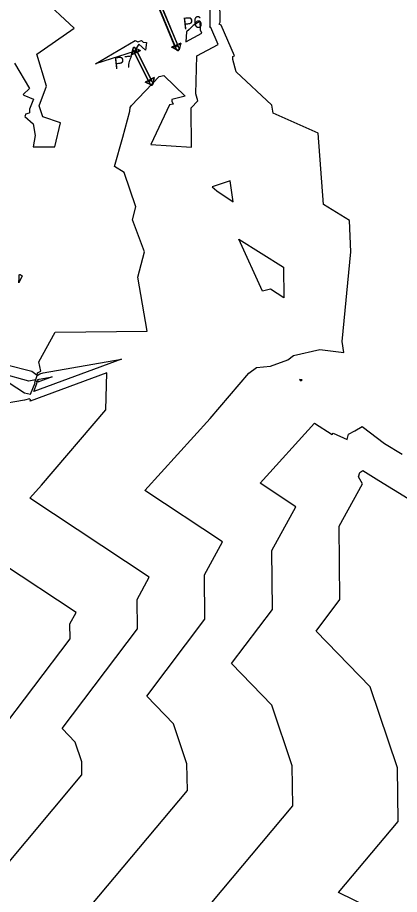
# Model space of a CAD drawing. Extents: x -549394 to -546608, y -1037055 to -1033629.
# Drawn here: x -547438 to -547324.6, y -1035525.4 to -1035265.1 of the extents above; entities that cross this region are included whole.
import ezdxf

# ---------------------------------------------------------------- set-up
doc = ezdxf.new("R2010")
doc.units = 0
for name, color, linetype in [('hlavni_vrst', 7, 'Continuous'), ('norm_vrst', 7, 'Continuous'), ('x_popis_C14', 7, 'Continuous'), ('x_propustek', 7, 'Continuous')]:
    doc.layers.add(name, color=color, linetype=linetype)

msp = doc.modelspace()

# ---------------------------------------------------------------- linework, layer by layer
at = {"layer": 'hlavni_vrst'}
for p, q in [((-547427.7, -1035371.77), (-547432.03, -1035373.37)), ((-547432.03, -1035373.37), (-547431.85, -1035372.89)), ((-547431.97, -1035372.6), (-547431.9, -1035372.55)), ((-547431.97, -1035372.82), (-547431.97, -1035372.6)), ((-547431.85, -1035372.89), (-547431.97, -1035372.82)), ((-547431.9, -1035372.55), (-547431.57, -1035372.45)), ((-547431.57, -1035372.45), (-547427.7, -1035371.77)), ((-547365.95, -1035403.31), (-547349.87, -1035385.5)), ((-547349.87, -1035385.5), (-547344.57, -1035388.84)), ((-547337.93, -1035387.82), (-547335.7, -1035386.54)), ((-547335.7, -1035386.54), (-547329.05, -1035391.52)), ((-547344.57, -1035388.84), (-547344.36, -1035388.52)), ((-547344.36, -1035388.52), (-547340.2, -1035390.38)), ((-547340.2, -1035390.38), (-547339.78, -1035388.83)), ((-547339.78, -1035388.83), (-547337.93, -1035387.82)), ((-547329.05, -1035391.52), (-547323.87, -1035394.76)), ((-547355.36, -1035410.32), (-547365.95, -1035403.31)), ((-547362.55, -1035423.36), (-547355.36, -1035410.32)), ((-547362.34, -1035440.8), (-547362.55, -1035423.36)), ((-547374.53, -1035456.91), (-547362.34, -1035440.8)), ((-547362.54, -1035469.25), (-547374.53, -1035456.91)), ((-547356.48, -1035487.24), (-547362.54, -1035469.25)), ((-547356.3, -1035499.12), (-547356.48, -1035487.24)), ((-547383.4, -1035531.44), (-547356.3, -1035499.12))]:
    msp.add_line(p, q, dxfattribs=at)
at = {"layer": 'norm_vrst'}
for p, q in [((-547380.81, -1035267.64), (-547380.88, -1035253.24)), ((-547421.19, -1035268.25), (-547432.95, -1035257.28)), ((-547377.89, -1035266.54), (-547377.92, -1035259.76)), ((-547383.75, -1035266.15), (-547385.92, -1035267.52)), ((-547383.74, -1035268.75), (-547383.75, -1035266.15)), ((-547378.18, -1035267.11), (-547377.89, -1035266.54)), ((-547432.32, -1035276.03), (-547421.19, -1035268.25)), ((-547387.88, -1035269.32), (-547388.08, -1035272.29)), ((-547387.06, -1035268.71), (-547387.88, -1035269.32)), ((-547385.92, -1035267.52), (-547387.06, -1035268.71)), ((-547383.77, -1035268.8), (-547383.74, -1035268.75)), ((-547383.71, -1035268.83), (-547383.77, -1035268.8)), ((-547383.31, -1035269.73), (-547383.71, -1035268.83)), ((-547380.97, -1035267.96), (-547380.81, -1035267.64)), ((-547380.66, -1035268.12), (-547380.97, -1035267.96)), ((-547378.46, -1035273.09), (-547380.66, -1035268.12)), ((-547377.61, -1035267.4), (-547378.18, -1035267.11)), ((-547373.61, -1035276.45), (-547377.61, -1035267.4)), ((-547414.86, -1035278.87), (-547403.07, -1035271.98)), ((-547403.07, -1035271.98), (-547402.33, -1035272.33)), ((-547402.33, -1035272.33), (-547401.26, -1035271.97)), ((-547401.26, -1035271.97), (-547400.7, -1035272.4)), ((-547388.08, -1035272.29), (-547383.31, -1035269.73)), ((-547402.04, -1035273.04), (-547403.41, -1035275.22)), ((-547400.06, -1035274.8), (-547402.04, -1035273.04)), ((-547400.7, -1035272.4), (-547399.73, -1035272.53)), ((-547399.73, -1035272.53), (-547400.06, -1035274.8)), ((-547384.79, -1035276.49), (-547378.46, -1035273.09)), ((-547429.44, -1035285.46), (-547432.32, -1035276.03)), ((-547403.41, -1035275.22), (-547414.86, -1035278.87)), ((-547385.1, -1035287.74), (-547384.79, -1035276.49)), ((-547374.1, -1035277.54), (-547374.08, -1035276.7)), ((-547374.08, -1035276.7), (-547373.61, -1035276.45)), ((-547438.93, -1035278.69), (-547434.43, -1035286.23)), ((-547373.07, -1035281.22), (-547374.1, -1035277.54)), ((-547404.2, -1035291.19), (-547395.97, -1035282.66)), ((-547395.97, -1035282.66), (-547394.56, -1035282.33)), ((-547394.56, -1035282.33), (-547388.3, -1035288.42)), ((-547362.51, -1035291.15), (-547373.07, -1035281.22)), ((-547434.43, -1035286.23), (-547436.33, -1035288)), ((-547431.59, -1035291.29), (-547429.44, -1035285.46)), ((-547384.51, -1035289.83), (-547385.1, -1035287.74)), ((-547436.33, -1035288), (-547436.27, -1035288.03)), ((-547436.27, -1035288.03), (-547436.19, -1035288.2)), ((-547436.19, -1035288.2), (-547433.28, -1035289.38)), ((-547433.28, -1035289.38), (-547434.45, -1035292.28)), ((-547388.3, -1035288.42), (-547392.24, -1035289.43)), ((-547392.24, -1035289.43), (-547392.22, -1035289.95)), ((-547392.22, -1035289.95), (-547391.81, -1035290.88)), ((-547386.51, -1035291.88), (-547384.51, -1035289.83)), ((-547434.45, -1035292.28), (-547434.5, -1035293.43)), ((-547430.55, -1035294.64), (-547431.59, -1035291.29)), ((-547406.73, -1035300.62), (-547404.64, -1035292.94)), ((-547404.64, -1035292.94), (-547404.6, -1035291.85)), ((-547404.6, -1035291.85), (-547404.2, -1035291.19)), ((-547392.94, -1035290.99), (-547398.47, -1035302.8)), ((-547391.81, -1035290.88), (-547392.94, -1035290.99)), ((-547386.34, -1035303.6), (-547386.51, -1035291.88)), ((-547362.1, -1035293.55), (-547362.51, -1035291.15)), ((-547435.54, -1035293.74), (-547435.86, -1035294.48)), ((-547435.86, -1035294.48), (-547433.33, -1035296.72)), ((-547435.54, -1035293.74), (-547434.5, -1035293.43)), ((-547425.27, -1035296.42), (-547430.55, -1035294.64)), ((-547348.8, -1035299.47), (-547362.1, -1035293.55)), ((-547433.33, -1035296.72), (-547432.75, -1035300.09)), ((-547426.92, -1035303.53), (-547425.27, -1035296.42)), ((-547432.75, -1035300.09), (-547433.38, -1035303.53)), ((-547409.24, -1035309.35), (-547406.73, -1035300.62)), ((-547347.19, -1035320.57), (-547348.8, -1035299.47)), ((-547433.38, -1035303.53), (-547426.92, -1035303.53)), ((-547398.47, -1035302.8), (-547386.34, -1035303.6)), ((-547406.39, -1035311.07), (-547409.24, -1035309.35)), ((-547402.86, -1035321.34), (-547406.39, -1035311.07)), ((-547374.89, -1035313.57), (-547380.23, -1035315.38)), ((-547374.05, -1035319.8), (-547374.89, -1035313.57)), ((-547380.23, -1035315.38), (-547378.83, -1035316.58)), ((-547378.83, -1035316.58), (-547374.05, -1035319.8)), ((-547403.9, -1035325.15), (-547402.86, -1035321.34)), ((-547339.51, -1035325.35), (-547347.19, -1035320.57)), ((-547400.32, -1035334.67), (-547403.9, -1035325.15)), ((-547339.08, -1035334.62), (-547339.51, -1035325.35)), ((-547372.31, -1035330.92), (-547359.1, -1035339.24)), ((-547365.27, -1035346.33), (-547372.31, -1035330.92)), ((-547402.34, -1035342.16), (-547400.32, -1035334.67)), ((-547341.62, -1035361.33), (-547339.08, -1035334.62)), ((-547359.1, -1035339.24), (-547358.95, -1035348.33)), ((-547436.65, -1035341.77), (-547437.66, -1035343.87)), ((-547437.66, -1035343.87), (-547437.55, -1035342.43)), ((-547437.55, -1035342.43), (-547437.52, -1035341.54)), ((-547437.52, -1035341.54), (-547437.29, -1035341.44)), ((-547437.29, -1035341.44), (-547437.24, -1035341.39)), ((-547437.24, -1035341.39), (-547436.65, -1035341.77)), ((-547399.54, -1035358.21), (-547402.34, -1035342.16)), ((-547362.88, -1035345.77), (-547365.27, -1035346.33)), ((-547365.27, -1035346.33), (-547365.27, -1035346.33)), ((-547358.95, -1035348.33), (-547362.88, -1035345.77)), ((-547362.88, -1035345.77), (-547362.88, -1035345.77)), ((-547431.66, -1035367.28), (-547426.86, -1035358.54)), ((-547426.86, -1035358.54), (-547399.54, -1035358.21)), ((-547341.16, -1035364.59), (-547341.62, -1035361.33)), ((-547357.82, -1035366.7), (-547356.05, -1035365.42)), ((-547356.05, -1035365.42), (-547348.25, -1035363.7)), ((-547348.25, -1035363.7), (-547341.16, -1035364.59)), ((-547441.58, -1035368.06), (-547433.73, -1035370.1)), ((-547407.19, -1035366.57), (-547433.16, -1035376.16)), ((-547431.11, -1035370.06), (-547431.66, -1035367.28)), ((-547430.42, -1035370.63), (-547407.19, -1035366.57)), ((-547362.92, -1035368.63), (-547357.82, -1035366.7)), ((-547434.67, -1035373.03), (-547442.43, -1035370.9)), ((-547411.55, -1035370.55), (-547434.3, -1035378.95)), ((-547433.73, -1035370.1), (-547432.23, -1035371.23)), ((-547432.23, -1035371.23), (-547432.06, -1035370.6)), ((-547432.21, -1035371.4), (-547431.36, -1035370.91)), ((-547432.06, -1035370.6), (-547431.11, -1035370.06)), ((-547431.36, -1035370.91), (-547430.42, -1035370.63)), ((-547411.85, -1035381.59), (-547411.55, -1035370.55)), ((-547380.83, -1035384.1), (-547369.34, -1035370.67)), ((-547369.34, -1035370.67), (-547367.1, -1035369.04)), ((-547367.1, -1035369.04), (-547362.92, -1035368.63)), ((-547443.07, -1035371.84), (-547435.93, -1035376.54)), ((-547432.65, -1035372.63), (-547434.67, -1035373.03)), ((-547434.14, -1035376.92), (-547432.81, -1035373.57)), ((-547433.16, -1035376.16), (-547432.28, -1035373.75)), ((-547432.93, -1035373.5), (-547432.65, -1035372.63)), ((-547432.81, -1035373.57), (-547432.93, -1035373.5)), ((-547432.68, -1035372.99), (-547432.55, -1035372.6)), ((-547432.16, -1035373.3), (-547432.68, -1035372.99)), ((-547432.55, -1035372.6), (-547432.38, -1035372)), ((-547432.38, -1035372), (-547432.3, -1035371.72)), ((-547432.32, -1035373.71), (-547432.16, -1035373.3)), ((-547432.28, -1035373.75), (-547432.32, -1035373.71)), ((-547432.3, -1035371.72), (-547432.21, -1035371.4)), ((-547353.94, -1035372.67), (-547354.27, -1035372.53)), ((-547354.27, -1035372.53), (-547354.13, -1035372.79)), ((-547354.13, -1035372.79), (-547353.82, -1035372.97)), ((-547353.48, -1035372.64), (-547353.94, -1035372.67)), ((-547353.82, -1035372.97), (-547353.48, -1035372.64)), ((-547435.93, -1035378.68), (-547448.48, -1035380.87)), ((-547435.93, -1035376.54), (-547434.14, -1035376.92)), ((-547434.46, -1035378.31), (-547435.93, -1035378.68)), ((-547434.17, -1035378.6), (-547434.46, -1035378.31)), ((-547434.3, -1035378.95), (-547434.17, -1035378.6)), ((-547430.92, -1035403.89), (-547411.85, -1035381.59)), ((-547400.18, -1035405.53), (-547380.83, -1035384.1)), ((-547336.39, -1035400.15), (-547335.52, -1035399.59)), ((-547335.52, -1035399.59), (-547330.74, -1035402.58)), ((-547336.81, -1035401.41), (-547336.39, -1035400.15)), ((-547335.6, -1035403.49), (-547336.81, -1035401.41)), ((-547434.41, -1035407.75), (-547430.92, -1035403.89)), ((-547342.57, -1035416.13), (-547335.6, -1035403.49)), ((-547330.74, -1035402.58), (-547322.05, -1035407.85)), ((-547377.12, -1035420.78), (-547400.18, -1035405.53)), ((-547398.89, -1035431.25), (-547434.41, -1035407.75)), ((-547342.31, -1035437.9), (-547342.57, -1035416.13)), ((-547382.53, -1035430.59), (-547377.12, -1035420.78)), ((-547420.65, -1035441.72), (-547442.43, -1035427.31)), ((-547382.37, -1035443.7), (-547382.53, -1035430.59)), ((-547402.51, -1035437.82), (-547398.89, -1035431.25)), ((-547402.4, -1035446.61), (-547402.51, -1035437.82)), ((-547349.39, -1035447.27), (-547342.31, -1035437.9)), ((-547422.49, -1035445.05), (-547420.65, -1035441.72)), ((-547399.66, -1035466.56), (-547382.37, -1035443.7)), ((-547424.79, -1035476.2), (-547402.4, -1035446.61)), ((-547422.44, -1035449.51), (-547422.49, -1035445.05)), ((-547333.36, -1035463.78), (-547349.39, -1035447.27)), ((-547448.7, -1035484.23), (-547422.44, -1035449.51)), ((-547325.25, -1035487.85), (-547333.36, -1035463.78)), ((-547391.72, -1035474.73), (-547399.66, -1035466.56)), ((-547387.71, -1035486.64), (-547391.72, -1035474.73)), ((-547420.91, -1035480.2), (-547424.79, -1035476.2)), ((-547418.94, -1035486.04), (-547420.91, -1035480.2)), ((-547418.88, -1035489.89), (-547418.94, -1035486.04)), ((-547387.59, -1035494.51), (-547387.71, -1035486.64)), ((-547325.01, -1035503.74), (-547325.25, -1035487.85)), ((-547464.74, -1035544.58), (-547418.88, -1035489.89)), ((-547424.07, -1035538.01), (-547387.59, -1035494.51)), ((-547342.73, -1035524.87), (-547325.01, -1035503.74)), ((-547325.82, -1035533.03), (-547342.73, -1035524.87))]:
    msp.add_line(p, q, dxfattribs=at)
at = {"layer": 'x_propustek'}
for p, q in [((-547390.99, -1035274.38), (-547395.78, -1035262.9)), ((-547390.92, -1035274.35), (-547395.71, -1035262.87)), ((-547390.16, -1035274.03), (-547394.95, -1035262.55)), ((-547390.09, -1035274), (-547394.88, -1035262.52)), ((-547404.16, -1035276.2), (-547403.73, -1035274.17)), ((-547404.16, -1035276.2), (-547401.47, -1035274.86)), ((-547403.35, -1035273.98), (-547403.73, -1035274.17)), ((-547398.73, -1035284.65), (-547403.61, -1035274.87)), ((-547403.35, -1035273.98), (-547401.47, -1035274.86)), ((-547397.99, -1035284.28), (-547402.87, -1035274.5)), ((-547397.92, -1035284.24), (-547402.8, -1035274.47)), ((-547401.89, -1035275.07), (-547402.07, -1035274.72)), ((-547401.8, -1035275.03), (-547401.89, -1035274.85)), ((-547389.52, -1035272.73), (-547392.29, -1035273.89)), ((-547390.47, -1035274.89), (-547392.29, -1035273.89)), ((-547391.94, -1035273.75), (-547391.87, -1035273.93)), ((-547391.85, -1035273.71), (-547391.7, -1035274.08)), ((-547391.76, -1035273.67), (-547391.68, -1035273.85)), ((-547390.47, -1035274.89), (-547390.08, -1035274.73)), ((-547389.52, -1035272.73), (-547390.08, -1035274.73)), ((-547390.05, -1035272.95), (-547389.97, -1035273.14)), ((-547389.95, -1035272.92), (-547389.8, -1035273.29)), ((-547389.86, -1035272.88), (-547389.79, -1035273.06)), ((-547403.73, -1035275.99), (-547403.91, -1035275.63)), ((-547403.82, -1035276.04), (-547403.91, -1035275.86)), ((-547403.64, -1035275.95), (-547403.73, -1035275.77)), ((-547398.79, -1035284.68), (-547403.67, -1035274.9)), ((-547401.98, -1035275.12), (-547402.07, -1035274.94)), ((-547397.44, -1035282.94), (-547400.12, -1035284.28)), ((-547398.24, -1035285.16), (-547400.12, -1035284.28)), ((-547399.79, -1035284.12), (-547399.7, -1035284.3)), ((-547399.7, -1035284.07), (-547399.52, -1035284.43)), ((-547399.61, -1035284.03), (-547399.52, -1035284.21)), ((-547398.24, -1035285.16), (-547397.87, -1035284.97)), ((-547397.95, -1035283.2), (-547397.86, -1035283.38)), ((-547397.44, -1035282.94), (-547397.87, -1035284.97)), ((-547397.86, -1035283.16), (-547397.68, -1035283.51)), ((-547397.77, -1035283.11), (-547397.68, -1035283.29))]:
    msp.add_line(p, q, dxfattribs=at)
for points in [[(-547403.57, -1035274.01), (-547403.59, -1035274.02), (-547403.6, -1035274.03), (-547403.63, -1035274.05), (-547403.64, -1035274.06), (-547403.67, -1035274.09), (-547403.69, -1035274.11), (-547403.75, -1035274.2), (-547403.77, -1035274.27), (-547403.79, -1035274.44), (-547403.79, -1035274.53), (-547403.75, -1035274.72), (-547403.72, -1035274.81), (-547403.63, -1035274.99), (-547403.57, -1035275.08), (-547403.45, -1035275.22), (-547403.38, -1035275.27), (-547403.23, -1035275.36), (-547403.16, -1035275.38), (-547403.07, -1035275.39), (-547403.06, -1035275.39), (-547403.02, -1035275.39), (-547403.01, -1035275.39), (-547402.96, -1035275.38), (-547402.93, -1035275.37), (-547402.9, -1035275.36)], [(-547403.54, -1035274.08), (-547403.56, -1035274.09), (-547403.58, -1035274.1), (-547403.62, -1035274.14), (-547403.63, -1035274.16), (-547403.66, -1035274.21), (-547403.68, -1035274.23), (-547403.7, -1035274.3), (-547403.7, -1035274.33), (-547403.71, -1035274.4), (-547403.71, -1035274.44), (-547403.71, -1035274.53), (-547403.71, -1035274.57), (-547403.68, -1035274.7), (-547403.65, -1035274.78), (-547403.57, -1035274.95), (-547403.51, -1035275.03), (-547403.43, -1035275.13), (-547403.39, -1035275.16), (-547403.33, -1035275.21), (-547403.3, -1035275.23), (-547403.23, -1035275.27), (-547403.2, -1035275.29), (-547403.14, -1035275.31), (-547403.11, -1035275.31), (-547403.06, -1035275.32), (-547403.03, -1035275.32), (-547402.98, -1035275.31), (-547402.96, -1035275.3), (-547402.91, -1035275.28), (-547402.89, -1035275.27), (-547402.86, -1035275.23), (-547402.84, -1035275.21), (-547402.81, -1035275.16), (-547402.8, -1035275.14), (-547402.78, -1035275.07), (-547402.77, -1035275.04), (-547402.76, -1035274.96), (-547402.76, -1035274.93), (-547402.76, -1035274.84), (-547402.77, -1035274.8), (-547402.8, -1035274.67), (-547402.83, -1035274.58), (-547402.91, -1035274.42), (-547402.96, -1035274.34), (-547403.05, -1035274.24), (-547403.08, -1035274.21), (-547403.14, -1035274.16), (-547403.18, -1035274.14), (-547403.24, -1035274.1), (-547403.27, -1035274.08), (-547403.33, -1035274.06), (-547403.36, -1035274.06), (-547403.42, -1035274.05), (-547403.45, -1035274.05), (-547403.5, -1035274.06), (-547403.52, -1035274.07), (-547403.54, -1035274.08)], [(-547402.9, -1035275.36), (-547402.89, -1035275.35), (-547402.87, -1035275.34), (-547402.85, -1035275.32), (-547402.84, -1035275.31), (-547402.8, -1035275.28), (-547402.78, -1035275.26), (-547402.73, -1035275.17), (-547402.7, -1035275.09), (-547402.68, -1035274.93), (-547402.69, -1035274.84), (-547402.72, -1035274.65), (-547402.76, -1035274.56), (-547402.85, -1035274.38), (-547402.9, -1035274.29), (-547403.03, -1035274.15), (-547403.1, -1035274.09), (-547403.24, -1035274.01), (-547403.32, -1035273.99), (-547403.4, -1035273.98), (-547403.42, -1035273.98), (-547403.45, -1035273.98), (-547403.47, -1035273.98), (-547403.52, -1035273.99), (-547403.55, -1035274), (-547403.57, -1035274.01)], [(-547390.83, -1035273.49), (-547390.84, -1035273.5), (-547390.86, -1035273.51), (-547390.88, -1035273.52), (-547390.9, -1035273.53), (-547390.93, -1035273.56), (-547390.96, -1035273.59), (-547391.01, -1035273.67), (-547391.04, -1035273.74), (-547391.08, -1035273.91), (-547391.08, -1035274), (-547391.05, -1035274.19), (-547391.03, -1035274.28), (-547390.95, -1035274.47), (-547390.9, -1035274.55), (-547390.78, -1035274.7), (-547390.72, -1035274.77), (-547390.58, -1035274.86), (-547390.51, -1035274.89), (-547390.42, -1035274.9), (-547390.4, -1035274.9), (-547390.37, -1035274.91), (-547390.35, -1035274.91), (-547390.31, -1035274.9), (-547390.28, -1035274.89), (-547390.25, -1035274.88)], [(-547390.28, -1035274.81), (-547390.25, -1035274.8), (-547390.23, -1035274.79), (-547390.19, -1035274.76), (-547390.18, -1035274.74), (-547390.14, -1035274.69), (-547390.13, -1035274.67), (-547390.11, -1035274.61), (-547390.1, -1035274.57), (-547390.08, -1035274.5), (-547390.08, -1035274.46), (-547390.08, -1035274.38), (-547390.08, -1035274.33), (-547390.1, -1035274.2), (-547390.12, -1035274.11), (-547390.19, -1035273.94), (-547390.24, -1035273.86), (-547390.32, -1035273.76), (-547390.35, -1035273.73), (-547390.41, -1035273.67), (-547390.44, -1035273.64), (-547390.5, -1035273.6), (-547390.53, -1035273.59), (-547390.59, -1035273.56), (-547390.62, -1035273.55), (-547390.68, -1035273.54), (-547390.7, -1035273.54), (-547390.75, -1035273.55), (-547390.78, -1035273.55), (-547390.82, -1035273.57), (-547390.84, -1035273.58), (-547390.88, -1035273.62), (-547390.9, -1035273.63), (-547390.93, -1035273.68), (-547390.94, -1035273.71), (-547390.97, -1035273.77), (-547390.98, -1035273.8), (-547390.99, -1035273.88), (-547391, -1035273.91), (-547391, -1035274), (-547391, -1035274.04), (-547390.98, -1035274.17), (-547390.96, -1035274.26), (-547390.88, -1035274.43), (-547390.84, -1035274.51), (-547390.75, -1035274.62), (-547390.73, -1035274.65), (-547390.67, -1035274.7), (-547390.64, -1035274.73), (-547390.57, -1035274.77), (-547390.54, -1035274.79), (-547390.48, -1035274.81), (-547390.45, -1035274.82), (-547390.4, -1035274.83), (-547390.37, -1035274.83), (-547390.32, -1035274.83), (-547390.3, -1035274.82), (-547390.28, -1035274.81)], [(-547390.25, -1035274.88), (-547390.23, -1035274.87), (-547390.22, -1035274.87), (-547390.19, -1035274.85), (-547390.18, -1035274.84), (-547390.14, -1035274.81), (-547390.12, -1035274.79), (-547390.06, -1035274.7), (-547390.03, -1035274.63), (-547390, -1035274.47), (-547390, -1035274.38), (-547390.02, -1035274.19), (-547390.05, -1035274.09), (-547390.13, -1035273.91), (-547390.18, -1035273.82), (-547390.29, -1035273.67), (-547390.36, -1035273.61), (-547390.5, -1035273.51), (-547390.57, -1035273.48), (-547390.65, -1035273.47), (-547390.67, -1035273.47), (-547390.7, -1035273.47), (-547390.72, -1035273.47), (-547390.77, -1035273.47), (-547390.8, -1035273.48), (-547390.83, -1035273.49)], [(-547398.69, -1035283.79), (-547398.71, -1035283.8), (-547398.72, -1035283.8), (-547398.75, -1035283.82), (-547398.76, -1035283.83), (-547398.79, -1035283.87), (-547398.81, -1035283.89), (-547398.87, -1035283.98), (-547398.89, -1035284.05), (-547398.91, -1035284.22), (-547398.91, -1035284.31), (-547398.87, -1035284.5), (-547398.84, -1035284.59), (-547398.75, -1035284.77), (-547398.69, -1035284.85), (-547398.57, -1035284.99), (-547398.5, -1035285.05), (-547398.35, -1035285.14), (-547398.28, -1035285.16), (-547398.19, -1035285.17), (-547398.18, -1035285.17), (-547398.14, -1035285.17), (-547398.13, -1035285.17), (-547398.08, -1035285.16), (-547398.05, -1035285.15), (-547398.02, -1035285.14)], [(-547398.06, -1035285.07), (-547398.03, -1035285.06), (-547398.01, -1035285.04), (-547397.98, -1035285.01), (-547397.96, -1035284.99), (-547397.93, -1035284.94), (-547397.92, -1035284.91), (-547397.9, -1035284.85), (-547397.89, -1035284.82), (-547397.88, -1035284.74), (-547397.88, -1035284.7), (-547397.88, -1035284.62), (-547397.89, -1035284.58), (-547397.92, -1035284.45), (-547397.95, -1035284.36), (-547398.03, -1035284.19), (-547398.08, -1035284.12), (-547398.17, -1035284.02), (-547398.2, -1035283.99), (-547398.26, -1035283.94), (-547398.3, -1035283.91), (-547398.36, -1035283.88), (-547398.39, -1035283.86), (-547398.45, -1035283.84), (-547398.48, -1035283.83), (-547398.54, -1035283.83), (-547398.57, -1035283.83), (-547398.62, -1035283.84), (-547398.64, -1035283.85), (-547398.68, -1035283.87), (-547398.7, -1035283.88), (-547398.74, -1035283.92), (-547398.75, -1035283.94), (-547398.78, -1035283.98), (-547398.8, -1035284.01), (-547398.82, -1035284.07), (-547398.82, -1035284.11), (-547398.83, -1035284.18), (-547398.83, -1035284.22), (-547398.83, -1035284.3), (-547398.83, -1035284.35), (-547398.8, -1035284.47), (-547398.77, -1035284.56), (-547398.69, -1035284.73), (-547398.63, -1035284.81), (-547398.55, -1035284.91), (-547398.51, -1035284.94), (-547398.45, -1035284.99), (-547398.42, -1035285.01), (-547398.35, -1035285.05), (-547398.32, -1035285.06), (-547398.26, -1035285.08), (-547398.23, -1035285.09), (-547398.17, -1035285.1), (-547398.15, -1035285.09), (-547398.1, -1035285.09), (-547398.08, -1035285.08), (-547398.06, -1035285.07)], [(-547398.02, -1035285.14), (-547398.01, -1035285.13), (-547397.99, -1035285.12), (-547397.97, -1035285.1), (-547397.96, -1035285.09), (-547397.92, -1035285.06), (-547397.9, -1035285.03), (-547397.85, -1035284.95), (-547397.82, -1035284.87), (-547397.8, -1035284.7), (-547397.81, -1035284.61), (-547397.84, -1035284.43), (-547397.88, -1035284.33), (-547397.97, -1035284.15), (-547398.02, -1035284.07), (-547398.15, -1035283.93), (-547398.22, -1035283.87), (-547398.36, -1035283.79), (-547398.44, -1035283.76), (-547398.52, -1035283.76), (-547398.54, -1035283.76), (-547398.57, -1035283.76), (-547398.59, -1035283.76), (-547398.64, -1035283.77), (-547398.67, -1035283.78), (-547398.69, -1035283.79)]]:
    msp.add_open_spline(points, degree=3, dxfattribs=at)

# ---------------------------------------------------------------- texts
at = {"layer": 'x_popis_C14'}
for s, p in [('P6', (-547388.69, -1035268.7)), ('P7', (-547409.15, -1035280.43))]:
    msp.add_text(s, height=3.5, rotation=6.4523, dxfattribs=at).set_placement(p)

doc.saveas('drawing.dxf')
